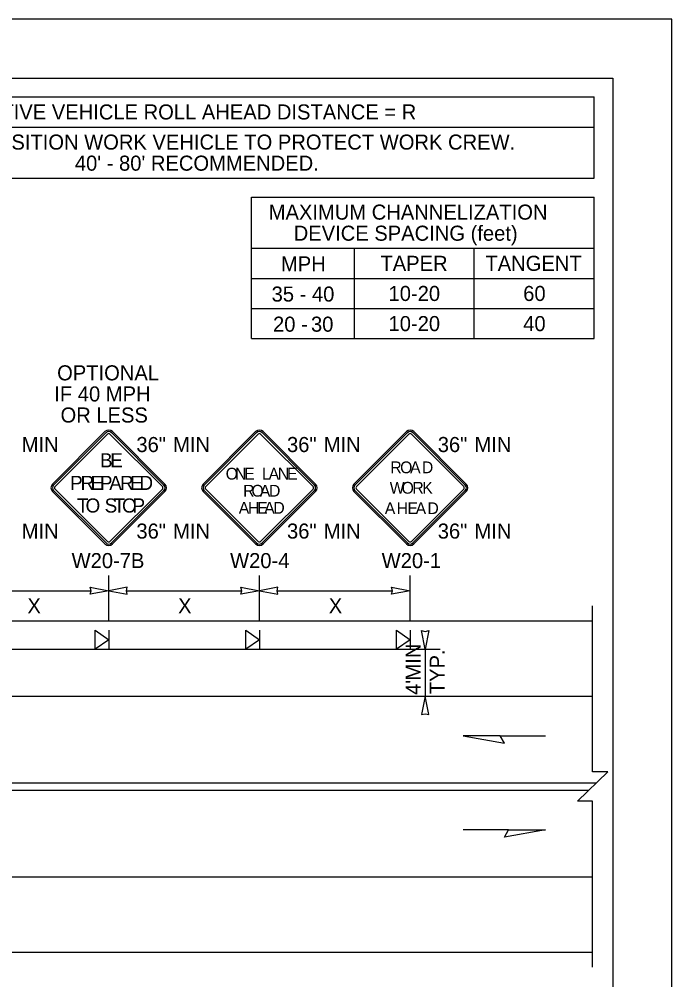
# Model space of a CAD drawing. Extents: x 99999.1 to 100095.7, y 99995 to 100010.7.
# Drawn here: x 100012.6 to 100016.06, y 100005.59 to 100010.69 of the extents above; entities that cross this region are included whole.
import ezdxf

# ---------------------------------------------------------------- set-up
doc = ezdxf.new("R2010")
doc.units = 0
for name, color, linetype in [('RD_ED_ShoulderPavedEdge', 7, 'Continuous'), ('RD_MK_LineDblYellowCenter', 7, 'Continuous'), ('RD_MK_LineEdgeWhite', 7, 'Continuous'), ('SH_GI_PlotLimits', 7, 'Continuous'), ('SH_GI_SheetBorder', 7, 'Continuous'), ('SH_TI_Tables', 7, 'Continuous'), ('TR_SN_ConstructionSigns', 7, 'Continuous'), ('TR_WZ_PortableSignMountBlk-Org', 7, 'Continuous'), ('TR_WZ_WorkZoneDetails', 7, 'Continuous'), ('TR_WZ_WorkZoneTextCurrent', 7, 'Continuous')]:
    doc.layers.add(name, color=color, linetype=linetype)

msp = doc.modelspace()

# ---------------------------------------------------------------- linework, layer by layer
at = {"layer": 'RD_ED_ShoulderPavedEdge'}
for p, q in [((100000.1076, 100007.4923), (100015.6424, 100007.4923)), ((100000.1076, 100005.7323), (100015.6424, 100005.7323))]:
    msp.add_line(p, q, dxfattribs=at)
at = {"layer": 'RD_MK_LineDblYellowCenter'}
for p, q in [((100012.2733, 100006.6323), (100015.6631, 100006.6323)), ((100012.2733, 100006.5923), (100015.6218, 100006.5923))]:
    msp.add_line(p, q, dxfattribs=at)
at = {"layer": 'RD_MK_LineEdgeWhite'}
for p, q in [((100000.1076, 100007.0923), (100015.6424, 100007.0923)), ((100000.1076, 100006.1323), (100015.6424, 100006.1323))]:
    msp.add_line(p, q, dxfattribs=at)
at = {"layer": 'SH_GI_PlotLimits'}
msp.add_lwpolyline([(99999.0625, 99999.6875), (100016.0625, 99999.6875), (100016.0625, 100010.6875), (99999.0625, 100010.6875)], close=True, dxfattribs=at)
at = {"layer": 'SH_GI_SheetBorder'}
for p, q in [((100000, 100010.375), (100015.75, 100010.375)), ((100015.75, 100010.375), (100015.75, 100000))]:
    msp.add_line(p, q, dxfattribs=at)
at = {"layer": 'SH_TI_Tables'}
for p, q in [((100011.4347, 100010.275), (100015.65, 100010.275)), ((100015.65, 100009.843), (100015.65, 100010.275)), ((100011.4347, 100010.115), (100015.65, 100010.115)), ((100011.4347, 100009.843), (100015.65, 100009.843)), ((100013.8318, 100009.743), (100015.65, 100009.743)), ((100013.8318, 100008.991), (100013.8318, 100009.743)), ((100015.65, 100008.991), (100015.65, 100009.743)), ((100013.8318, 100009.471), (100015.65, 100009.471)), ((100014.3773, 100008.991), (100014.3773, 100009.471)), ((100015.0136, 100008.991), (100015.0136, 100009.471)), ((100013.8318, 100009.311), (100014.3773, 100009.311)), ((100014.3773, 100009.311), (100015.0136, 100009.311)), ((100015.0136, 100009.311), (100015.65, 100009.311)), ((100013.8318, 100009.151), (100014.3773, 100009.151)), ((100014.3773, 100009.151), (100015.0136, 100009.151)), ((100015.0136, 100009.151), (100015.6472, 100009.151)), ((100013.8318, 100008.991), (100015.65, 100008.991))]:
    msp.add_line(p, q, dxfattribs=at)
at = {"layer": 'TR_SN_ConstructionSigns'}
for p, q in [((100013.0535, 100008.4972), (100012.775, 100008.2188)), ((100013.059, 100008.4917), (100012.7806, 100008.2132)), ((100012.7883, 100008.2055), (100013.0667, 100008.4839)), ((100013.08, 100008.4839), (100013.3584, 100008.2055)), ((100013.3661, 100008.2132), (100013.0877, 100008.4917)), ((100013.3717, 100008.2188), (100013.0932, 100008.4972)), ((100013.8532, 100008.4972), (100013.5747, 100008.2188)), ((100013.8587, 100008.4917), (100013.5803, 100008.2132)), ((100013.588, 100008.2055), (100013.8664, 100008.4839)), ((100013.8797, 100008.4839), (100014.1581, 100008.2055)), ((100014.1658, 100008.2132), (100013.8874, 100008.4917)), ((100014.1714, 100008.2188), (100013.8929, 100008.4972)), ((100014.6535, 100008.4972), (100014.375, 100008.2188)), ((100014.659, 100008.4917), (100014.3806, 100008.2132)), ((100014.3883, 100008.2055), (100014.6667, 100008.4839)), ((100014.68, 100008.4839), (100014.9584, 100008.2055)), ((100014.9661, 100008.2132), (100014.6877, 100008.4917)), ((100014.9717, 100008.2188), (100014.6932, 100008.4972)), ((100012.775, 100008.179), (100013.0535, 100007.9006)), ((100012.7806, 100008.1845), (100013.059, 100007.9061)), ((100013.0667, 100007.9138), (100012.7883, 100008.1923)), ((100013.3584, 100008.1923), (100013.08, 100007.9138)), ((100013.0877, 100007.9061), (100013.3661, 100008.1845)), ((100013.0932, 100007.9006), (100013.3717, 100008.179)), ((100013.5747, 100008.179), (100013.8532, 100007.9006)), ((100013.5803, 100008.1845), (100013.8587, 100007.9061)), ((100013.8664, 100007.9138), (100013.588, 100008.1923)), ((100014.1581, 100008.1923), (100013.8797, 100007.9138)), ((100013.8874, 100007.9061), (100014.1658, 100008.1845)), ((100013.8929, 100007.9006), (100014.1714, 100008.179)), ((100014.375, 100008.179), (100014.6535, 100007.9006)), ((100014.3806, 100008.1845), (100014.659, 100007.9061)), ((100014.6667, 100007.9138), (100014.3883, 100008.1923)), ((100014.9584, 100008.1923), (100014.68, 100007.9138)), ((100014.6877, 100007.9061), (100014.9661, 100008.1845)), ((100014.6932, 100007.9006), (100014.9717, 100008.179))]:
    msp.add_line(p, q, dxfattribs=at)
for centre, radius, start, end in [((100013.0733, 100008.4773), 0.0281, 45, 135), ((100013.873, 100008.4773), 0.0281, 45, 135), ((100014.6733, 100008.4773), 0.0281, 45, 135), ((100013.0733, 100008.4773), 0.0203, 45, 135), ((100013.0733, 100008.4773), 0.00937, 45, 135), ((100013.873, 100008.4773), 0.0203, 45, 135), ((100013.873, 100008.4773), 0.00937, 45, 135), ((100014.6733, 100008.4773), 0.0203, 45, 135), ((100014.6733, 100008.4773), 0.00937, 45, 135), ((100012.7949, 100008.1989), 0.0281, 135, 225), ((100012.7949, 100008.1989), 0.0203, 135, 225), ((100012.7949, 100008.1989), 0.00937, 135, 225), ((100013.3518, 100008.1989), 0.00937, 315, 45), ((100013.3518, 100008.1989), 0.0203, 315, 45), ((100013.3518, 100008.1989), 0.0281, 315, 45), ((100013.5946, 100008.1989), 0.0281, 135, 225), ((100013.5946, 100008.1989), 0.0203, 135, 225), ((100013.5946, 100008.1989), 0.00937, 135, 225), ((100014.1515, 100008.1989), 0.00937, 315, 45), ((100014.1515, 100008.1989), 0.0203, 315, 45), ((100014.1515, 100008.1989), 0.0281, 315, 45), ((100014.3949, 100008.1989), 0.0281, 135, 225), ((100014.3949, 100008.1989), 0.0203, 135, 225), ((100014.3949, 100008.1989), 0.00937, 135, 225), ((100014.9518, 100008.1989), 0.00937, 315, 45), ((100014.9518, 100008.1989), 0.0203, 315, 45), ((100014.9518, 100008.1989), 0.0281, 315, 45), ((100013.0733, 100007.9205), 0.0281, 225, 315), ((100013.0733, 100007.9205), 0.0203, 225, 315), ((100013.0733, 100007.9205), 0.00937, 225, 315), ((100013.873, 100007.9205), 0.0281, 225, 315), ((100013.873, 100007.9205), 0.0203, 225, 315), ((100013.873, 100007.9205), 0.00937, 225, 315), ((100014.6733, 100007.9205), 0.0281, 225, 315), ((100014.6733, 100007.9205), 0.0203, 225, 315), ((100014.6733, 100007.9205), 0.00937, 225, 315)]:
    msp.add_arc(centre, radius, start, end, dxfattribs=at)
at = {"layer": 'TR_WZ_PortableSignMountBlk-Org'}
for p, q in [((100013.0733, 100007.4422), (100013.0733, 100007.3422)), ((100013.8733, 100007.4422), (100013.8733, 100007.3422)), ((100014.6733, 100007.4422), (100014.6733, 100007.3422))]:
    msp.add_line(p, q, dxfattribs=at)
for points in [[(100013.0733, 100007.3923), (100013.0015, 100007.3422), (100013.0015, 100007.4422)], [(100013.8733, 100007.3923), (100013.8015, 100007.3422), (100013.8015, 100007.4422)], [(100014.6733, 100007.3923), (100014.6015, 100007.3422), (100014.6015, 100007.4422)]]:
    msp.add_lwpolyline(points, close=True, dxfattribs=at)
at = {"layer": 'TR_WZ_WorkZoneDetails'}
for p, q in [((100013.0733, 100007.4923), (100013.0733, 100007.7323)), ((100013.8733, 100007.4923), (100013.8733, 100007.7323)), ((100014.6733, 100007.4921), (100014.6733, 100007.7323)), ((100012.3671, 100007.6523), (100012.9796, 100007.6523)), ((100013.1671, 100007.6523), (100013.7796, 100007.6523)), ((100013.9671, 100007.6523), (100014.5796, 100007.6523)), ((100012.2733, 100007.3422), (100014.6733, 100007.3422)), ((100014.6733, 100007.3422), (100014.8333, 100007.3422)), ((100014.7533, 100007.3422), (100014.7533, 100007.0923)), ((100014.6733, 100007.0923), (100014.8333, 100007.0923)), ((100015.1513, 100006.8816), (100015.3924, 100006.8816)), ((100015.1959, 100006.3816), (100014.9548, 100006.3816))]:
    msp.add_line(p, q, dxfattribs=at)
for points in [[(100013.0733, 100007.6523), (100012.9751, 100007.6331), (100012.9796, 100007.6523), (100012.9751, 100007.6716)], [(100013.0733, 100007.6523), (100013.1716, 100007.6331), (100013.1671, 100007.6523), (100013.1716, 100007.6716)], [(100013.8733, 100007.6523), (100013.7751, 100007.6331), (100013.7796, 100007.6523), (100013.7751, 100007.6716)], [(100013.8733, 100007.6523), (100013.9716, 100007.6331), (100013.9671, 100007.6523), (100013.9716, 100007.6716)], [(100014.6733, 100007.6523), (100014.5751, 100007.6331), (100014.5796, 100007.6523), (100014.5751, 100007.6716)], [(100014.7533, 100007.3422), (100014.7341, 100007.4405), (100014.7533, 100007.436), (100014.7726, 100007.4405)], [(100014.7533, 100007.0923), (100014.7341, 100006.9941), (100014.7533, 100006.9986), (100014.7726, 100006.9941)], [(100014.9548, 100006.8816), (100015.1736, 100006.843), (100015.1513, 100006.8816)], [(100015.3924, 100006.3816), (100015.1736, 100006.343), (100015.1959, 100006.3816)]]:
    msp.add_lwpolyline(points, close=True, dxfattribs=at)
msp.add_lwpolyline([(100015.6424, 100005.6523), (100015.6424, 100006.5349), (100015.5624, 100006.5349), (100015.7225, 100006.6898), (100015.6424, 100006.6898), (100015.6424, 100007.5723)], dxfattribs=at)

# ---------------------------------------------------------------- texts
at = {"layer": 'SH_TI_Tables'}
for s, p in [('PROTECTIVE VEHICLE ROLL AHEAD DISTANCE = R', (100012.0577, 100010.155)), ('STRATEGICALLY POSITION WORK VEHICLE TO PROTECT WORK CREW.', (100011.4984, 100009.995)), ("40' - 80'", (100012.8935, 100009.883)), ('RECOMMENDED.', (100013.297, 100009.883))]:
    msp.add_text(s, height=0.08, rotation=360, dxfattribs=at).set_placement(p)
for s, p in [('MAXIMUM CHANNELIZATION', (100013.9227, 100009.623)), ('DEVICE SPACING (feet)', (100014.0553, 100009.511)), ('MPH', (100013.9878, 100009.3479)), ('TAPER', (100014.5157, 100009.351)), ('TANGENT', (100015.0731, 100009.351)), ('10-20', (100014.5588, 100009.191)), ('60', (100015.2737, 100009.191)), ('35', (100013.9381, 100009.1879)), ('- 40', (100014.0869, 100009.1879)), ('20', (100013.9456, 100009.0279)), ('30', (100014.1472, 100009.0279)), ('10-20', (100014.5588, 100009.031)), ('40', (100015.2737, 100009.031)), ('-', (100014.0944, 100009.0279))]:
    msp.add_text(s, height=0.08, dxfattribs=at).set_placement(p)
at = {"layer": 'TR_SN_ConstructionSigns'}
for s, height, p in [('OPTIONAL', 0.08, (100012.7994, 100008.7694)), ('IF 40 MPH', 0.08, (100012.7843, 100008.6574)), ('OR LESS', 0.08, (100012.8175, 100008.5454)), ('B', 0.075, (100013.0271, 100008.3074)), ('E', 0.075, (100013.0814, 100008.3074)), ('O', 0.0625, (100013.6943, 100008.2426)), ('N', 0.0625, (100013.7437, 100008.2426)), ('E', 0.0625, (100013.7924, 100008.2426)), ('L', 0.0625, (100013.8868, 100008.2426)), ('A', 0.0625, (100013.9224, 100008.2426)), ('N', 0.0625, (100013.9712, 100008.2426)), ('E', 0.0625, (100014.0199, 100008.2426)), ('R', 0.0625, (100014.5683, 100008.2762)), ('O', 0.0625, (100014.6204, 100008.2762)), ('A', 0.0625, (100014.6732, 100008.2762)), ('D', 0.0625, (100014.7359, 100008.2762)), ('P', 0.075, (100012.8684, 100008.1874)), ('R', 0.075, (100012.9237, 100008.1874)), ('E', 0.075, (100012.9769, 100008.1874)), ('P', 0.075, (100013.0264, 100008.1874)), ('A', 0.075, (100013.0763, 100008.1874)), ('R', 0.075, (100013.1335, 100008.1874)), ('E', 0.075, (100013.1868, 100008.1874)), ('D', 0.075, (100013.2362, 100008.1874)), ('R', 0.0625, (100013.7868, 100008.152)), ('O', 0.0625, (100013.8312, 100008.152)), ('A', 0.0625, (100013.8755, 100008.152)), ('D', 0.0625, (100013.9243, 100008.152)), ('W', 0.0625, (100014.565, 100008.1676)), ('O', 0.0625, (100014.6282, 100008.1676)), ('R', 0.0625, (100014.6855, 100008.1676)), ('K', 0.0625, (100014.7379, 100008.1676)), ('T', 0.075, (100012.9051, 100008.0674)), ('O', 0.075, (100012.9502, 100008.0674)), ('S', 0.075, (100013.0516, 100008.0674)), ('T', 0.075, (100013.0988, 100008.0674)), ('O', 0.075, (100013.1439, 100008.0674)), ('P', 0.075, (100013.1996, 100008.0674)), ('A', 0.0625, (100013.7637, 100008.0614)), ('H', 0.0625, (100013.8124, 100008.0614)), ('E', 0.0625, (100013.8612, 100008.0614)), ('A', 0.0625, (100013.8987, 100008.0614)), ('D', 0.0625, (100013.9474, 100008.0614)), ('A', 0.0625, (100014.539, 100008.0591)), ('H', 0.0625, (100014.6015, 100008.0591)), ('E', 0.0625, (100014.659, 100008.0591)), ('A', 0.0625, (100014.7027, 100008.0591)), ('D', 0.0625, (100014.7652, 100008.0591))]:
    msp.add_text(s, height=height, dxfattribs=at).set_placement(p)
for s, p in [('MIN', (100012.6114, 100008.3887)), ('36"', (100013.2201, 100008.3887)), ('MIN', (100013.4151, 100008.3887)), ('36"', (100014.0198, 100008.3887)), ('MIN', (100014.2148, 100008.3887)), ('36"', (100014.8201, 100008.3887)), ('MIN', (100015.0151, 100008.3887)), ('MIN', (100012.6114, 100007.9291)), ('36"', (100013.2201, 100007.9291)), ('MIN', (100013.4151, 100007.9291)), ('36"', (100014.0198, 100007.9291)), ('MIN', (100014.2148, 100007.9291)), ('36"', (100014.8201, 100007.9291)), ('MIN', (100015.0151, 100007.9291)), ('W20-7B', (100012.8763, 100007.7723)), ('W20-4', (100013.7176, 100007.7723)), ('W20-1', (100014.5224, 100007.7723))]:
    msp.add_text(s, height=0.08, rotation=360, dxfattribs=at).set_placement(p)
at = {"layer": 'TR_WZ_WorkZoneTextCurrent'}
for p in [(100012.6416, 100007.5323), (100013.4416, 100007.5323), (100014.2416, 100007.5323)]:
    msp.add_text('X', height=0.08, dxfattribs=at).set_placement(p)
for s, p in [('MIN', (100014.7293, 100007.1754)), ('TYP.', (100014.8573, 100007.1026)), ("4'", (100014.7293, 100007.0989))]:
    msp.add_text(s, height=0.08, rotation=90, dxfattribs=at).set_placement(p)

doc.saveas('drawing.dxf')
